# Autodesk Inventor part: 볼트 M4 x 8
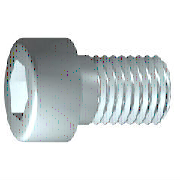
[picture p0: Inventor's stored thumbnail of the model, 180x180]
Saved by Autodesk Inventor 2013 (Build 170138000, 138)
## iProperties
IsCustomPart: 0
Created: 2012-02
Part Number: 볼트 M4 x 8
Material: 스테인리스강
Description: 6각 소켓 머리 캡 나사
Document SubType Name: Modeling
Standard: ISO 4762
Designer: mduedu
Standard Revision: Fourth edition 2004-03-01
Standards Organization: ISO
Language: ko-KR
Size Designation: M4 x 8
Categories: <MemberInstance><Categories><Category DisplayName="조임쇠" InternalName="e4da775c-781d-43d5-af7c-5136215cf5a6" Mnemonic="FSTN"><Category DisplayName="볼트" InternalN
Density: 8.08 g/cm^3
Mass: 1.89105 g
Surface Area: 2.80587 cm^2
Volume: 0.234041 cm^3
Author: mduedu
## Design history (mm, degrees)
sketch "스케치1"
  geometry: L1 (-1, 0)-(8, 0); L2 (8, 0)-(8, 2); L3 (8, 2)-(1.75, 2); L4 (1.75, 2)-(1.32, 2); L5 (1.32, 2)-(0, 2); L6 (0, 2)-(0, 3.5); L7 (0, 3.5)-(-4, 3.5); L8 (-4, 3.5)-(-4, 1.732); L9 (-4, 1.732)-(-2, 1.732); L10 (-2, 1.732)-(-1, 0); L11 (-6.4, 0)-(10.4, 0) reference; L12 (0, -0.7)-(0, 4.2) reference; L13 (1.75, 2)-(0, 2)
  constraints: 22 end point, 6 parallel, 2 collinear, 2 perpendicular, 1 horizontal, 1 point on line
  dimensions: "d1" = 6.25 distance from line of L3.end L2 (= GEL); "d2" = 0.42952 distance of L4.end L3.end (computed from GAL); "d3" = 4 distance between parallel lines of L8 L6 (= KOH); "d4" = 2 distance of L8.end L9.end (= INTI); "d5" = 60 deg angle of L10 L1; "d6" = 4 diameter of L3 L1 (= GD); "d7" = 4 diameter of L5 L1 (= BDM); "d8" = 3.4641 diameter of L9 L1 (= 1.1547 x SW); "d9" = 7 diameter of L7 L1 (= KOD); "d26" = 8 distance between parallel lines of L12 L2 (= NLG)
revolve "본체" sketch "스케치1" stored, may be unused: angle "d10" = 90 deg
sketch "스케치2"
  geometry: L1 (0, -4.9)-(0, 4.9) reference; L2 (-4.9, 0)-(4.9, 0) reference; L3 (1.732, 0)-(0.866, -1.5); L4 (0.866, -1.5)-(-0.866, -1.5); L5 (-0.866, -1.5)-(-1.732, 0); L6 (-1.732, 0)-(-0.866, 1.5); L7 (-0.866, 1.5)-(0.866, 1.5); L8 (0.866, 1.5)-(1.732, 0); 2 further points
  constraints: 12 end point, 1 coincident, 1 horizontal alignment, 1 point on line, 12 other
extrude "슬롯" join sketch "스케치2" stored distance "d11" = 10; taper "d12" = 0 deg
workplane "Work Plane1"
fillet "Fillet2" dims "d30" = 0.1 (= R)
body "Solid1"
fillet "모깎기1" dims "d17" = 0.4 (= RR)
feature "스레드" dims "d13" = 6.25 (= GEL), "d14" = 0
chamfer "모따기1" distance "d15" = 0.42941 (= -0.5 x SPD + 0.5 x GD); stored, may be unused: second distance "d16" = 0.42941 (= GUL), angle "d27" = 45 deg
other parameters: "GD" = 4 [user parameter; used in 2 equation terms], "NLG" = 8 [user parameter; used in 1 equation term], "GEL" = 6.25 [user parameter; used in 2 equation terms], "KOD" = 7 [user parameter; used in 1 equation term], "KOH" = 4 [user parameter; used in 1 equation term], "INTI" = 2 [user parameter; used in 1 equation term], "GAL" = 0.42941 (= 0.61345 x PTC) [user parameter; used in 1 equation term], "GUL" = 0.42941 (= 0.61345 x PTC) [user parameter; used in 1 equation term], "BDM" = 4 (= NND) [user parameter; used in 1 equation term], "SW" = 3 [user parameter; used in 2 equation terms], "RR" = 0.4 [user parameter; used in 1 equation term], "SPD" = 3.14117 (= NND - 1.2269 x PTC) [user parameter; used in 1 equation term], "d19" = 0, "d28" = 0, "d29" = 0, "R" = 0.1 [user parameter; used in 1 equation term], "TOA" = 30 deg [user parameter], "GD1" = 3.14117 (= THREADDIA - 1.2269 x PTC) [user parameter], "THREADDIA" = 4 [user parameter; used in 1 equation term], "FAWI" = 45 deg [user parameter], "TPU" = 14.28571 (computed from PTC) [user parameter], "PTC" = 0.7 [user parameter; used in 5 equation terms], "NND" = 4 [user parameter; used in 2 equation terms], "E0" = 3.465 (= 1.155 x SW) [user parameter]
